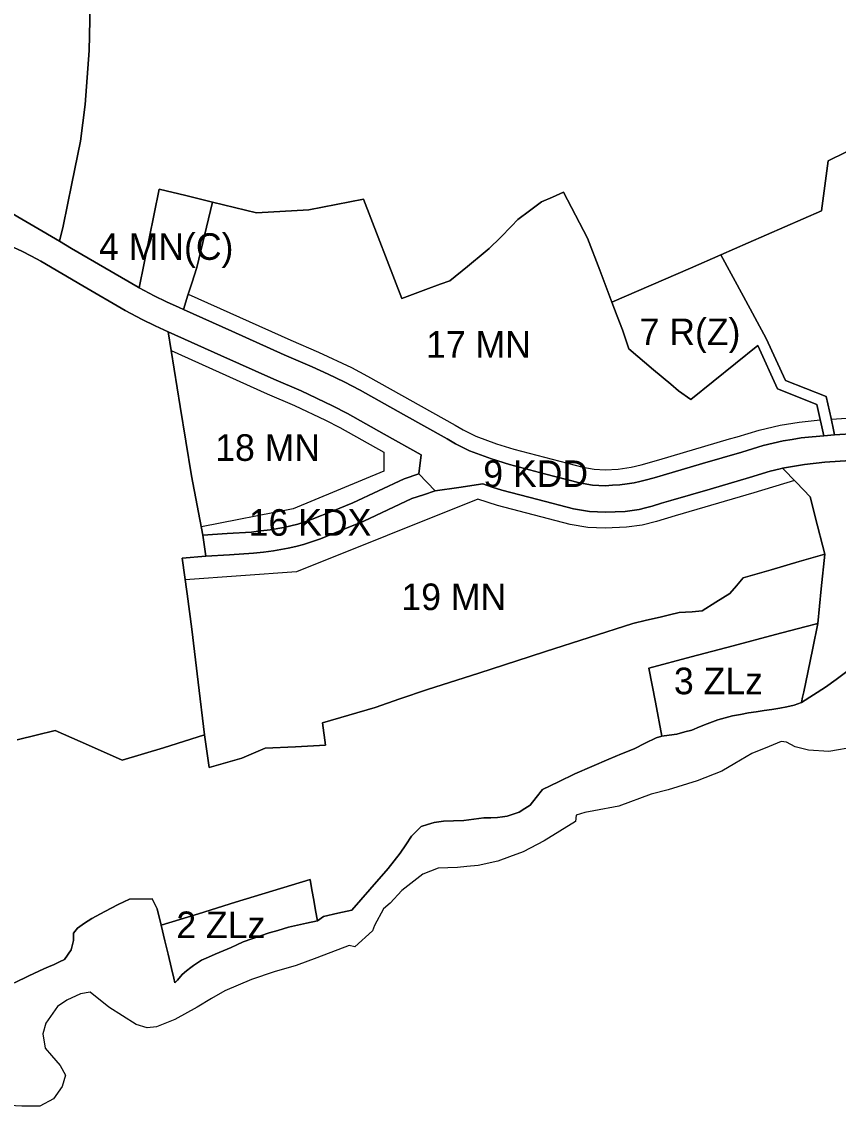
# Model space of a CAD drawing. Extents: x -294445 to -292055, y 21869 to 23693.
# Drawn here: x -292783 to -292476, y 22190.5 to 22598.3 of the extents above; entities that cross this region are included whole.
import ezdxf

# ---------------------------------------------------------------- set-up
doc = ezdxf.new("R2010")
doc.units = 0
for name, color, linetype in [('linie_rozgraniczajace', 7, 'Continuous'), ('linie_zabudowy_nieprzekraczalne', 7, 'Continuous'), ('oznaczenia_przeznaczen', 7, 'Continuous')]:
    doc.layers.add(name, color=color, linetype=linetype)

msp = doc.modelspace()

# ---------------------------------------------------------------- linework, layer by layer
at = {"layer": 'linie_rozgraniczajace'}
for points in [[(-292757.32, 22604.665), (-292757.59, 22587.46), (-292758.385, 22577.335), (-292759.18, 22567.21), (-292760.055, 22560.305), (-292760.93, 22553.4), (-292764.205, 22537.43), (-292767.48, 22521.46), (-292768.799, 22515.737), (-292789.634, 22527.91)], [(-292768.799, 22515.737), (-292767.48, 22521.46), (-292764.205, 22537.43), (-292760.93, 22553.4), (-292760.055, 22560.305), (-292759.18, 22567.21), (-292758.385, 22577.335), (-292757.59, 22587.46), (-292757.32, 22604.665)], [(-292473.11, 22549.255), (-292479.86, 22545.93), (-292481.105, 22536.585), (-292482.35, 22527.24), (-292496.103, 22521.207), (-292509.856, 22515.174), (-292520.147, 22510.66), (-292531.59, 22505.64), (-292546.34, 22499.225), (-292561.09, 22492.81), (-292565.69, 22504.88), (-292570.29, 22516.95), (-292574.775, 22525.565), (-292579.26, 22534.18), (-292583.445, 22532.345), (-292587.63, 22530.51), (-292592.045, 22527.23), (-292596.46, 22523.95), (-292598.83, 22521.41), (-292603.017, 22517.185), (-292607.204, 22512.959), (-292608.75, 22511.7), (-292615.38, 22506.3), (-292622.01, 22500.9), (-292625.655, 22499.564), (-292631.07, 22497.58), (-292640.13, 22494.26), (-292654.48, 22531.585), (-292675.063, 22527.495), (-292694.719, 22526.465), (-292711.243, 22530.481), (-292721.259, 22532.915), (-292731.275, 22535.349), (-292735.086, 22516.815), (-292738.898, 22498.28), (-292739.262, 22498.478), (-292764.243, 22513.074), (-292768.799, 22515.737)], [(-292444.844, 22445.015), (-292477.478, 22442.897), (-292477.856, 22444.893), (-292478.709, 22449.085), (-292480.59, 22457.33), (-292488.21, 22460.345), (-292495.83, 22463.36), (-292499.445, 22471.26), (-292503.06, 22479.16), (-292511.603, 22494.91), (-292520.147, 22510.66), (-292509.856, 22515.174), (-292496.103, 22521.207), (-292482.35, 22527.24), (-292481.105, 22536.585), (-292479.86, 22545.93), (-292473.11, 22549.255)], [(-292789.634, 22527.91), (-292768.799, 22515.737), (-292764.243, 22513.074), (-292739.262, 22498.478), (-292738.898, 22498.28), (-292733.245, 22495.221), (-292728.535, 22493.004), (-292723.826, 22490.788), (-292722.213, 22490.065), (-292704.06, 22481.932), (-292684.294, 22473.075), (-292673.837, 22468.559), (-292667.785, 22465.709), (-292661.734, 22462.859), (-292655.815, 22459.793), (-292639.43, 22450.601), (-292623.044, 22441.409), (-292619.893, 22439.552), (-292614.642, 22436.963), (-292606.424, 22433.939), (-292599.667, 22431.764), (-292586.51, 22428.339), (-292573.353, 22424.915), (-292568.429, 22424.045), (-292563.635, 22423.828), (-292560.875, 22423.976), (-292558.115, 22424.124), (-292555.431, 22424.505), (-292552.747, 22424.885), (-292550.671, 22425.366), (-292548.595, 22425.846), (-292545.203, 22426.839), (-292541.811, 22427.832), (-292527.045, 22432.164), (-292512.279, 22436.496), (-292504.207, 22438.953), (-292500.458, 22439.831), (-292496.708, 22440.71), (-292493.338, 22441.243), (-292489.968, 22441.776), (-292485.844, 22442.199), (-292481.478, 22442.637), (-292477.478, 22442.897), (-292444.844, 22445.015)], [(-292787.374, 22514.014), (-292782.899, 22512.059), (-292779.361, 22510.159), (-292775.823, 22508.258), (-292759.977, 22499), (-292744.131, 22489.742), (-292737.757, 22486.292), (-292732.879, 22483.996), (-292728, 22481.7), (-292725.724, 22467.66), (-292723.448, 22453.62), (-292721.339, 22440.61), (-292719.23, 22427.6), (-292717.04, 22416.42), (-292714.85, 22405.24), (-292713.785, 22397.291), (-292722.641, 22396.573), (-292720.825, 22383.201), (-292719.01, 22369.83), (-292716.62, 22349.94), (-292714.237, 22330.1), (-292729.74, 22325.315), (-292745.25, 22320.58), (-292757.87, 22326.21), (-292770.49, 22331.84), (-292784.655, 22328.23)], [(-292632.881, 22435.461), (-292646.722, 22443.226), (-292660.563, 22450.99), (-292666.166, 22453.893), (-292677.95, 22459.443), (-292688.258, 22463.895), (-292708.129, 22472.797), (-292728, 22481.7), (-292732.879, 22483.996), (-292737.757, 22486.292), (-292744.131, 22489.742), (-292759.977, 22499), (-292775.823, 22508.258), (-292779.361, 22510.159), (-292782.899, 22512.059), (-292787.374, 22514.014)], [(-292444.252, 22435.03), (-292481.025, 22432.64), (-292488.676, 22431.856), (-292496.923, 22430.389), (-292497.849, 22430.172), (-292501.608, 22429.291), (-292509.416, 22426.914), (-292524.206, 22422.576), (-292538.996, 22418.237), (-292542.483, 22417.211), (-292545.971, 22416.186), (-292548.422, 22415.558), (-292550.873, 22414.931), (-292553.515, 22414.549), (-292556.156, 22414.167), (-292559.892, 22413.992), (-292563.627, 22413.817), (-292566.58, 22413.951), (-292569.532, 22414.085), (-292575.543, 22415.149), (-292589.002, 22418.654), (-292602.461, 22422.158), (-292606.073, 22423.321), (-292609.685, 22424.484), (-292618.643, 22423.178), (-292627.601, 22421.873), (-292633.713, 22428.275), (-292632.881, 22435.461)], [(-292472.82, 22353.97), (-292476.825, 22351.01), (-292480.83, 22348.05), (-292485.325, 22345.18), (-292489.82, 22342.31), (-292489.404, 22344.336), (-292488.989, 22346.362), (-292487.51, 22353.57), (-292485.625, 22362.795), (-292483.74, 22372.02), (-292482.39, 22385.08), (-292481.04, 22398.14), (-292481.906, 22401.525), (-292483.766, 22408.791), (-292486.55, 22419.67), (-292491.736, 22425.029), (-292496.923, 22430.389), (-292488.676, 22431.856), (-292481.025, 22432.64), (-292444.252, 22435.03)], [(-292501.227, 22392.235), (-292490.688, 22395.318), (-292481.04, 22398.14), (-292482.39, 22385.08), (-292483.74, 22372.02), (-292488.574, 22370.741), (-292499.608, 22367.823), (-292515.475, 22363.625), (-292531.343, 22359.428), (-292547.21, 22355.23), (-292544.775, 22342.415), (-292542.34, 22329.6), (-292544.46, 22329.07), (-292548.605, 22326.99), (-292552.75, 22324.91), (-292557.51, 22322.95), (-292562.27, 22320.99), (-292568.685, 22318.22), (-292575.1, 22315.45), (-292581.17, 22312.51), (-292587.24, 22309.57), (-292589.56, 22306.645), (-292591.88, 22303.72), (-292593.905, 22302.395), (-292595.93, 22301.07), (-292598.185, 22300.3), (-292600.44, 22299.53), (-292602.255, 22299.3), (-292604.07, 22299.07), (-292606.69, 22298.995), (-292609.31, 22298.92), (-292613.055, 22298.455), (-292616.8, 22297.99), (-292620.62, 22297.84), (-292624.44, 22297.69), (-292627.94, 22297.2), (-292630.39, 22296.445), (-292632.84, 22295.69), (-292636.41, 22292.02), (-292638.595, 22288.835), (-292640.78, 22285.65), (-292645.28, 22279.91), (-292652.11, 22272.055), (-292658.94, 22264.2), (-292664.215, 22263.05), (-292669.49, 22261.9), (-292671.82, 22260.23), (-292672.515, 22264.105), (-292673.21, 22267.98), (-292673.905, 22271.855), (-292674.6, 22275.73), (-292688.598, 22271.455), (-292702.595, 22267.18), (-292716.593, 22262.905), (-292730.59, 22258.63), (-292732.06, 22264.77), (-292733.92, 22268.49), (-292742.52, 22268.32), (-292746.71, 22266.41), (-292751.705, 22263.75), (-292756.7, 22261.09), (-292759.385, 22259.305), (-292762.07, 22257.52), (-292763.59, 22255.63), (-292763.58, 22252.84), (-292764.41, 22249.33), (-292766.86, 22245.72), (-292768.815, 22244.75), (-292770.77, 22243.78), (-292772.875, 22242.94), (-292774.714, 22242.216), (-292780.355, 22239.515), (-292785.73, 22236.93)], [(-292784.655, 22328.23), (-292770.49, 22331.84), (-292757.87, 22326.21), (-292745.25, 22320.58), (-292729.74, 22325.315), (-292714.237, 22330.1), (-292712.49, 22317.92), (-292706.34, 22319.665), (-292700.19, 22321.41), (-292695.82, 22323.26), (-292691.45, 22325.11), (-292680.129, 22325.685), (-292668.808, 22326.26), (-292669.926, 22334.609), (-292660.038, 22337.534), (-292650.15, 22340.46), (-292640.794, 22343.637), (-292630.39, 22347.17), (-292611.095, 22353.395), (-292591.8, 22359.62), (-292586.09, 22361.47), (-292569.675, 22366.765), (-292553.26, 22372.06), (-292548.095, 22373.235), (-292542.93, 22374.41), (-292539.405, 22375.26), (-292535.88, 22376.11), (-292533.43, 22376.27), (-292530.98, 22376.43), (-292527.21, 22376.81), (-292521.985, 22380.07), (-292516.76, 22383.33), (-292514.285, 22386.235), (-292511.81, 22389.14), (-292501.227, 22392.235)], [(-292772.875, 22242.94), (-292770.77, 22243.78), (-292768.815, 22244.75), (-292766.86, 22245.72), (-292764.41, 22249.33), (-292763.58, 22252.84), (-292763.59, 22255.63), (-292762.07, 22257.52), (-292759.385, 22259.305), (-292756.7, 22261.09), (-292751.705, 22263.75), (-292746.71, 22266.41), (-292742.52, 22268.32), (-292733.92, 22268.49), (-292732.06, 22264.77), (-292730.59, 22258.63), (-292729.174, 22252.71), (-292727.97, 22247.677), (-292726.683, 22242.295), (-292725.801, 22238.608), (-292725.38, 22236.85), (-292724.48, 22237.88), (-292722.623, 22240.008), (-292721, 22241.4), (-292719.458, 22242.733), (-292718.373, 22243.443), (-292715.35, 22245.4), (-292712.82, 22246.555), (-292710.29, 22247.71), (-292707.28, 22248.925), (-292704.27, 22250.14), (-292702.13, 22251.163), (-292699.75, 22252.3), (-292689.945, 22255.652), (-292686.725, 22256.63), (-292682.74, 22257.84), (-292679.355, 22258.615), (-292675.97, 22259.39), (-292671.82, 22260.23), (-292669.49, 22261.9), (-292664.215, 22263.05), (-292658.94, 22264.2), (-292652.11, 22272.055), (-292645.28, 22279.91), (-292640.78, 22285.65), (-292638.595, 22288.835), (-292636.41, 22292.02), (-292632.84, 22295.69), (-292630.39, 22296.445), (-292627.94, 22297.2), (-292624.44, 22297.69), (-292620.62, 22297.84), (-292616.8, 22297.99), (-292613.055, 22298.455), (-292609.31, 22298.92), (-292606.69, 22298.995), (-292604.07, 22299.07), (-292602.255, 22299.3), (-292600.44, 22299.53), (-292598.185, 22300.3), (-292595.93, 22301.07), (-292593.905, 22302.395), (-292591.88, 22303.72), (-292589.56, 22306.645), (-292587.24, 22309.57), (-292581.17, 22312.51), (-292575.1, 22315.45), (-292568.685, 22318.22), (-292562.27, 22320.99), (-292557.51, 22322.95), (-292552.75, 22324.91), (-292548.605, 22326.99), (-292544.46, 22329.07), (-292542.34, 22329.6), (-292539.54, 22330.03), (-292536.74, 22330.46), (-292533.716, 22331.27), (-292531.1, 22331.97), (-292528.185, 22333.145), (-292525.27, 22334.32), (-292521.31, 22335.81), (-292518.565, 22336.575), (-292515.82, 22337.34), (-292512.805, 22337.86), (-292509.79, 22338.38), (-292506.838, 22338.815), (-292503.885, 22339.25), (-292500.933, 22339.685), (-292497.98, 22340.12), (-292495.375, 22340.665), (-292492.582, 22341.265), (-292489.82, 22342.31), (-292485.325, 22345.18), (-292480.83, 22348.05), (-292476.825, 22351.01), (-292472.82, 22353.97)], [(-292469.43, 22325.63), (-292479.56, 22323.84), (-292487.2, 22324.36), (-292492.15, 22325.69), (-292495.42, 22327.35), (-292497.5, 22327.62), (-292501.95, 22325.83), (-292508.54, 22323.12), (-292514.92, 22319.35), (-292519.75, 22316.49), (-292529.07, 22312.84), (-292539.92, 22309.42), (-292546.4, 22307.84), (-292558.46, 22303.29), (-292567.94, 22301.54), (-292571.28, 22300.92), (-292574.59, 22300.01), (-292574.77, 22297.61), (-292586.55, 22290.36), (-292594.42, 22286.2), (-292599.56, 22284.29), (-292603.97, 22282.66), (-292611.37, 22281.06), (-292615.6, 22280.68), (-292619.2, 22280.3), (-292626.39, 22279.96), (-292632.16, 22277.77), (-292640.13, 22271.62), (-292644.45, 22266.84), (-292647.04, 22264.76), (-292650.34, 22258.51), (-292651.18, 22256.47), (-292657.74, 22250.39), (-292659.93, 22250.94), (-292672.02, 22246.29), (-292679.8, 22243.43), (-292688.13, 22241), (-292696.6, 22238.15), (-292706.62, 22233.92), (-292711.67, 22231.06), (-292717.06, 22227.74), (-292725.48, 22223.12), (-292732.37, 22220.33), (-292735.9, 22219.94), (-292740.02, 22221.22), (-292750.25, 22227.81), (-292757.26, 22233.38), (-292760.88, 22232.76), (-292765.99, 22230.45), (-292769.54, 22227.97), (-292773.91, 22221.79), (-292775.02, 22217.74), (-292774.13, 22212.34), (-292771.78, 22209.58), (-292768.49, 22205.83), (-292766.59, 22202.21), (-292767.78, 22197.95), (-292771.03, 22193.26), (-292776.21, 22190.55), (-292782.91, 22190.48), (-292790.11, 22190.93)], [(-292785.73, 22236.93), (-292780.355, 22239.515), (-292774.714, 22242.216), (-292772.875, 22242.94)]]:
    msp.add_lwpolyline(points, dxfattribs=at)
for points in [[(-292738.898, 22498.28), (-292735.086, 22516.815), (-292731.275, 22535.349), (-292721.259, 22532.915), (-292711.243, 22530.481), (-292717.21, 22505.93), (-292719.08, 22500), (-292720.52, 22495.435), (-292722.213, 22490.065), (-292723.826, 22490.788), (-292728.535, 22493.004), (-292733.245, 22495.221)], [(-292722.213, 22490.065), (-292720.52, 22495.435), (-292719.08, 22500), (-292717.21, 22505.93), (-292711.243, 22530.481), (-292694.719, 22526.465), (-292675.063, 22527.495), (-292654.48, 22531.585), (-292640.13, 22494.26), (-292631.07, 22497.58), (-292625.655, 22499.564), (-292622.01, 22500.9), (-292615.38, 22506.3), (-292608.75, 22511.7), (-292607.204, 22512.959), (-292603.017, 22517.185), (-292598.83, 22521.41), (-292596.46, 22523.95), (-292592.045, 22527.23), (-292587.63, 22530.51), (-292583.445, 22532.345), (-292579.26, 22534.18), (-292574.775, 22525.565), (-292570.29, 22516.95), (-292565.69, 22504.88), (-292561.09, 22492.81), (-292559.1, 22487.595), (-292557.11, 22482.38), (-292554.77, 22475.28), (-292545.425, 22467.42), (-292538.994, 22462.011), (-292536.08, 22459.56), (-292531.5, 22456.18), (-292506.271, 22476.565), (-292498.798, 22460.233), (-292484.021, 22454.386), (-292481.478, 22442.637), (-292485.844, 22442.199), (-292489.968, 22441.776), (-292493.338, 22441.243), (-292496.708, 22440.71), (-292500.458, 22439.831), (-292504.207, 22438.953), (-292512.279, 22436.496), (-292527.045, 22432.164), (-292541.811, 22427.832), (-292545.203, 22426.839), (-292548.595, 22425.846), (-292550.671, 22425.366), (-292552.747, 22424.885), (-292555.431, 22424.505), (-292558.115, 22424.124), (-292560.875, 22423.976), (-292563.635, 22423.828), (-292568.429, 22424.045), (-292573.353, 22424.915), (-292586.51, 22428.339), (-292599.667, 22431.764), (-292606.424, 22433.939), (-292614.642, 22436.963), (-292619.893, 22439.552), (-292623.044, 22441.409), (-292639.43, 22450.601), (-292655.815, 22459.793), (-292661.734, 22462.859), (-292667.785, 22465.709), (-292673.837, 22468.559), (-292684.294, 22473.075), (-292704.06, 22481.932)], [(-292561.09, 22492.81), (-292546.34, 22499.225), (-292531.59, 22505.64), (-292520.147, 22510.66), (-292511.603, 22494.91), (-292503.06, 22479.16), (-292499.445, 22471.26), (-292495.83, 22463.36), (-292488.21, 22460.345), (-292480.59, 22457.33), (-292478.709, 22449.085), (-292477.856, 22444.893), (-292477.478, 22442.897), (-292481.478, 22442.637), (-292484.021, 22454.386), (-292498.798, 22460.233), (-292506.271, 22476.565), (-292531.5, 22456.18), (-292536.08, 22459.56), (-292538.994, 22462.011), (-292545.425, 22467.42), (-292554.77, 22475.28), (-292557.11, 22482.38), (-292559.1, 22487.595)], [(-292728, 22481.7), (-292708.129, 22472.797), (-292688.258, 22463.895), (-292677.95, 22459.443), (-292666.166, 22453.893), (-292660.563, 22450.99), (-292646.722, 22443.226), (-292632.881, 22435.461), (-292633.713, 22428.275), (-292639.245, 22426.442), (-292648.859, 22421.925), (-292658.473, 22417.407), (-292666.16, 22414.307), (-292673.846, 22411.207), (-292676.549, 22410.285), (-292679.252, 22409.363), (-292681.856, 22408.753), (-292684.46, 22408.144), (-292689.566, 22407.276), (-292693.105, 22406.825), (-292696.644, 22406.375), (-292705.747, 22405.807), (-292714.85, 22405.24), (-292717.04, 22416.42), (-292719.23, 22427.6), (-292721.339, 22440.61), (-292723.448, 22453.62), (-292725.724, 22467.66)], [(-292722.641, 22396.573), (-292713.785, 22397.291), (-292704.837, 22397.848), (-292695.889, 22398.406), (-292692.14, 22398.884), (-292688.39, 22399.361), (-292685.633, 22399.83), (-292682.877, 22400.298), (-292679.96, 22400.981), (-292677.043, 22401.663), (-292674.051, 22402.684), (-292670.613, 22403.875), (-292662.733, 22407.092), (-292654.406, 22410.479), (-292645.341, 22414.739), (-292636.275, 22418.998), (-292631.938, 22420.436), (-292627.601, 22421.873), (-292618.643, 22423.178), (-292609.685, 22424.484), (-292606.073, 22423.321), (-292602.461, 22422.158), (-292589.002, 22418.654), (-292575.543, 22415.149), (-292569.532, 22414.085), (-292566.58, 22413.951), (-292563.627, 22413.817), (-292559.892, 22413.992), (-292556.156, 22414.167), (-292553.515, 22414.549), (-292550.873, 22414.931), (-292548.422, 22415.558), (-292545.971, 22416.186), (-292542.483, 22417.211), (-292538.996, 22418.237), (-292524.206, 22422.576), (-292509.416, 22426.914), (-292501.608, 22429.291), (-292497.849, 22430.172), (-292496.923, 22430.389), (-292491.736, 22425.029), (-292486.55, 22419.67), (-292483.766, 22408.791), (-292481.906, 22401.525), (-292481.04, 22398.14), (-292490.688, 22395.318), (-292501.227, 22392.235), (-292511.81, 22389.14), (-292514.285, 22386.235), (-292516.76, 22383.33), (-292521.985, 22380.07), (-292527.21, 22376.81), (-292530.98, 22376.43), (-292533.43, 22376.27), (-292535.88, 22376.11), (-292539.405, 22375.26), (-292542.93, 22374.41), (-292548.095, 22373.235), (-292553.26, 22372.06), (-292569.675, 22366.765), (-292586.09, 22361.47), (-292591.8, 22359.62), (-292611.095, 22353.395), (-292630.39, 22347.17), (-292640.794, 22343.637), (-292650.15, 22340.46), (-292660.038, 22337.534), (-292669.926, 22334.609), (-292668.808, 22326.26), (-292680.129, 22325.685), (-292691.45, 22325.11), (-292695.82, 22323.26), (-292700.19, 22321.41), (-292706.34, 22319.665), (-292712.49, 22317.92), (-292714.237, 22330.1), (-292716.62, 22349.94), (-292719.01, 22369.83), (-292720.825, 22383.201)], [(-292714.85, 22405.24), (-292705.747, 22405.807), (-292696.644, 22406.375), (-292693.105, 22406.825), (-292689.566, 22407.276), (-292684.46, 22408.144), (-292681.856, 22408.753), (-292679.252, 22409.363), (-292676.549, 22410.285), (-292673.846, 22411.207), (-292666.16, 22414.307), (-292658.473, 22417.407), (-292648.859, 22421.925), (-292639.245, 22426.442), (-292633.713, 22428.275), (-292627.601, 22421.873), (-292631.938, 22420.436), (-292636.275, 22418.998), (-292645.341, 22414.739), (-292654.406, 22410.479), (-292662.733, 22407.092), (-292670.613, 22403.875), (-292674.051, 22402.684), (-292677.043, 22401.663), (-292679.96, 22400.981), (-292682.877, 22400.298), (-292685.633, 22399.83), (-292688.39, 22399.361), (-292692.14, 22398.884), (-292695.889, 22398.406), (-292704.837, 22397.848), (-292713.785, 22397.291)], [(-292547.21, 22355.23), (-292531.343, 22359.428), (-292515.475, 22363.625), (-292499.608, 22367.823), (-292488.574, 22370.741), (-292483.74, 22372.02), (-292485.625, 22362.795), (-292487.51, 22353.57), (-292488.989, 22346.362), (-292489.404, 22344.336), (-292489.82, 22342.31), (-292492.582, 22341.265), (-292495.375, 22340.665), (-292497.98, 22340.12), (-292500.933, 22339.685), (-292503.885, 22339.25), (-292506.838, 22338.815), (-292509.79, 22338.38), (-292512.805, 22337.86), (-292515.82, 22337.34), (-292518.565, 22336.575), (-292521.31, 22335.81), (-292525.27, 22334.32), (-292528.185, 22333.145), (-292531.1, 22331.97), (-292533.716, 22331.27), (-292536.74, 22330.46), (-292539.54, 22330.03), (-292542.34, 22329.6), (-292544.775, 22342.415)], [(-292730.59, 22258.63), (-292716.593, 22262.905), (-292702.595, 22267.18), (-292688.598, 22271.455), (-292674.6, 22275.73), (-292673.905, 22271.855), (-292673.21, 22267.98), (-292672.515, 22264.105), (-292671.82, 22260.23), (-292675.97, 22259.39), (-292679.355, 22258.615), (-292682.74, 22257.84), (-292686.725, 22256.63), (-292689.945, 22255.652), (-292699.75, 22252.3), (-292702.13, 22251.163), (-292704.27, 22250.14), (-292707.28, 22248.925), (-292710.29, 22247.71), (-292712.82, 22246.555), (-292715.35, 22245.4), (-292718.373, 22243.443), (-292719.458, 22242.733), (-292721, 22241.4), (-292722.623, 22240.008), (-292724.48, 22237.88), (-292725.38, 22236.85), (-292725.801, 22238.608), (-292726.683, 22242.295), (-292727.97, 22247.677), (-292729.174, 22252.71)]]:
    msp.add_lwpolyline(points, close=True, dxfattribs=at)
at = {"layer": 'linie_zabudowy_nieprzekraczalne'}
for points in [[(-292478.651, 22448.833), (-292408.647, 22453.378), (-292399.773, 22454.1), (-292245.491, 22468.964), (-292244.6, 22466.296), (-292244.6, 22466.296), (-292208.258, 22478.276), (-292219.557, 22503.736), (-292225.508, 22516.339), (-292230.157, 22528.975), (-292237.814, 22556.744), (-292244.621, 22581.395), (-292250.308, 22601.766), (-292257.313, 22625.56), (-292261.649, 22640.762), (-292272.438, 22678.471), (-292275.057, 22688.917), (-292284.695, 22745.774), (-292290.496, 22784.531), (-292295.967, 22812.331)], [(-292720.397, 22495.826), (-292681.878, 22478.567), (-292671.368, 22474.029), (-292659.075, 22468.239), (-292652.967, 22465.075), (-292620.053, 22446.61), (-292617.039, 22444.834), (-292612.273, 22442.484), (-292604.468, 22439.613), (-292597.99, 22437.527), (-292572.073, 22430.782), (-292567.768, 22430.021), (-292563.66, 22429.835), (-292558.698, 22430.102), (-292553.847, 22430.789), (-292550.115, 22431.653), (-292543.498, 22433.59), (-292516.883, 22441.398)], [(-292726.851, 22474.61), (-292690.675, 22458.403), (-292680.419, 22453.974), (-292668.825, 22448.513), (-292663.411, 22445.709), (-292646.831, 22436.407), (-292646.853, 22429.29), (-292680.909, 22415.137), (-292680.909, 22415.137), (-292680.909, 22415.137), (-292680.909, 22415.137), (-292680.909, 22415.137), (-292715.463, 22408.367)], [(-292516.883, 22441.398), (-292513.997, 22442.244), (-292505.767, 22444.75), (-292497.863, 22446.602), (-292490.743, 22447.728), (-292482.757, 22448.546)], [(-292492.48, 22425.798), (-292507.697, 22421.165), (-292537.305, 22412.48), (-292544.38, 22410.399), (-292549.697, 22409.039), (-292555.585, 22408.187), (-292563.622, 22407.811), (-292570.194, 22408.109), (-292576.824, 22409.283), (-292604.138, 22416.394), (-292611.566, 22418.786), (-292679.716, 22391.461), (-292721.539, 22388.462)]]:
    msp.add_lwpolyline(points, dxfattribs=at)

# ---------------------------------------------------------------- texts
at = {"layer": 'oznaczenia_przeznaczen'}
for s, p in [('4 MN(C)', (-292753.926, 22508.745)), ('7 R(Z)', (-292550.673, 22476.678)), ('17 MN', (-292630.961, 22471.936)), ('18 MN', (-292710.243, 22433.162)), ('9 KDD', (-292609.46, 22423.339)), ('16 KDX', (-292697.635, 22405.007)), ('19 MN', (-292640.24, 22377.052)), ('3 ZLz', (-292537.776, 22345.411)), ('2 ZLz', (-292724.863, 22253.72))]:
    msp.add_text(s, height=10, dxfattribs=at).set_placement(p)

doc.saveas('drawing.dxf')
